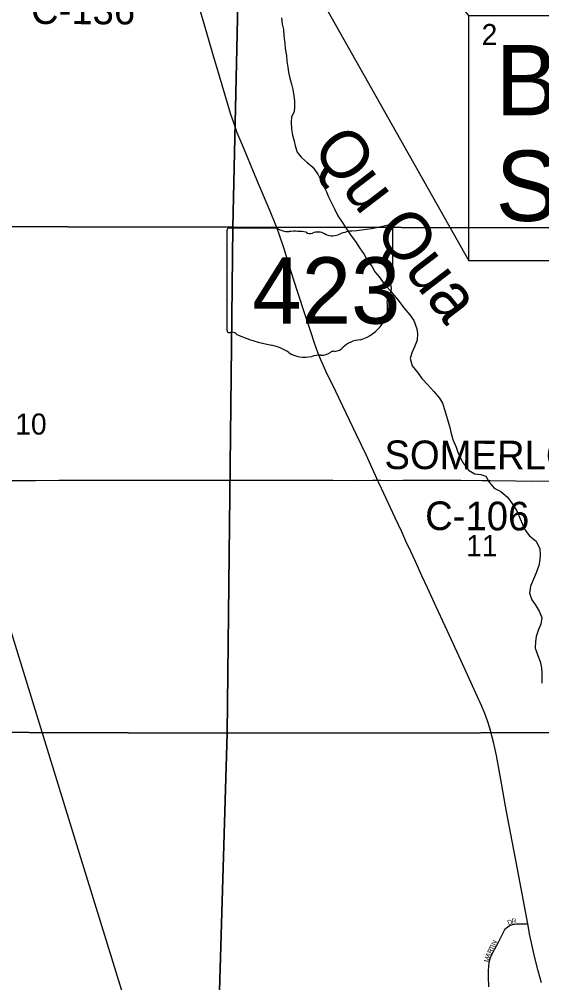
# Model space of a CAD drawing. Extents: x -97 to 34, y -21 to 22.
# Drawn here: x 6.147 to 7.185, y 14.954 to 16.869 of the extents above; entities that cross this region are included whole.
import ezdxf

# ---------------------------------------------------------------- set-up
doc = ezdxf.new("R2010")
doc.units = 0
for name, color, linetype in [('GM_X_County_Road', 7, 'Continuous'), ('GM_X_County_Road_Text', 7, 'Continuous'), ('GM_X_Minor_River', 7, 'Continuous'), ('GM_X_Minor_River_Text', 7, 'Continuous'), ('GM_X_Rail_Line', 7, 'Continuous'), ('GM_X_Section', 7, 'Continuous'), ('GM_X_Section_Text', 7, 'Continuous'), ('GM_X_State_Route', 7, 'Continuous'), ('GM_X_State_Shield', 7, 'Continuous'), ('GM_X_Township_Subdivision', 7, 'Continuous'), ('GM_X_Township_Subdivision_Text', 7, 'Continuous'), ('SH_Text', 7, 'Continuous')]:
    doc.layers.add(name, color=color, linetype=linetype)

msp = doc.modelspace()

# ---------------------------------------------------------------- linework, layer by layer
at = {"layer": 'GM_X_County_Road'}
for points in [[(6.0738, 15.9525), (6.1795, 15.9528), (6.2261, 15.9533), (6.2821, 15.9532), (6.366, 15.9535), (6.397, 15.9534), (6.4343, 15.9535), (6.5027, 15.9533), (6.5493, 15.9535), (6.5897, 15.9535), (6.6581, 15.9534), (6.7171, 15.9533), (6.77, 15.9531), (6.8197, 15.953), (6.8492, 15.9533), (6.8593, 15.9531)], [(6.8593, 15.9531), (6.8656, 15.9531), (6.8783, 15.953)], [(6.8783, 15.953), (6.8784, 15.953), (6.9095, 15.9531), (6.9344, 15.9533), (6.9655, 15.9533), (7.0245, 15.9532), (7.0672, 15.9528)], [(7.0672, 15.9528), (7.0836, 15.9526), (7.1333, 15.9518), (7.1644, 15.9517), (7.2017, 15.9518), (7.2328, 15.9521), (7.2825, 15.9526), (7.3074, 15.9525), (7.3187, 15.9525)]]:
    msp.add_lwpolyline(points, dxfattribs=at)
at = {"layer": 'GM_X_Minor_River'}
for points in [[(6.6681, 16.872), (6.6698, 16.8598), (6.672, 16.8492), (6.6729, 16.8366), (6.675, 16.8218), (6.6756, 16.8116), (6.6781, 16.7968), (6.679, 16.7865), (6.6808, 16.7744), (6.6821, 16.7641), (6.685, 16.7527), (6.6882, 16.7402), (6.6911, 16.7299), (6.6928, 16.717), (6.6939, 16.7075), (6.6944, 16.6954), (6.6932, 16.6855), (6.6885, 16.6754), (6.6872, 16.6651), (6.6881, 16.6507), (6.6903, 16.6393), (6.6935, 16.6275), (6.6953, 16.6176), (6.6992, 16.6051), (6.7071, 16.5955), (6.719, 16.5847), (6.7307, 16.5755), (6.7403, 16.5617), (6.7473, 16.5483), (6.7532, 16.5357), (6.7576, 16.5262), (6.7617, 16.5167), (6.7675, 16.5045), (6.7734, 16.4926), (6.7804, 16.4785)], [(6.7804, 16.4785), (6.7875, 16.4682), (6.796, 16.4552), (6.8068, 16.4391), (6.8153, 16.428), (6.8231, 16.415), (6.8328, 16.402), (6.8379, 16.3917), (6.8487, 16.3771), (6.8539, 16.3676), (6.8632, 16.3569), (6.8717, 16.3442), (6.8833, 16.3312), (6.8919, 16.3205), (6.9001, 16.3109), (6.9116, 16.2956), (6.9235, 16.2817), (6.9313, 16.2706), (6.9372, 16.2543), (6.9385, 16.2448), (6.938, 16.2315), (6.9329, 16.2183), (6.9274, 16.2067), (6.9238, 16.1953), (6.9278, 16.1805), (6.9401, 16.1663), (6.9475, 16.1556), (6.9591, 16.1429), (6.971, 16.1295), (6.9822, 16.1165), (6.9885, 16.1061), (6.9932, 16.0921), (6.9961, 16.0806), (6.9997, 16.0696), (7.003, 16.0582), (7.0058, 16.0464), (7.0091, 16.0342), (7.0153, 16.019), (7.0186, 16.0091), (7.0248, 15.9961), (7.03, 15.9866), (7.0401, 15.9732), (7.0525, 15.9658), (7.0646, 15.9645), (7.0744, 15.9613), (7.081, 15.9495), (7.0911, 15.9376), (7.1039, 15.9306), (7.1173, 15.9198), (7.1281, 15.9049), (7.1363, 15.8911), (7.1425, 15.8766), (7.1473, 15.8656), (7.1524, 15.8541), (7.1613, 15.843), (7.1744, 15.8322), (7.1814, 15.817), (7.1824, 15.8048), (7.1819, 15.795), (7.1798, 15.784), (7.1747, 15.7693), (7.1688, 15.7565), (7.1633, 15.7426), (7.1613, 15.7286), (7.1656, 15.7156), (7.1723, 15.7061), (7.1801, 15.6931), (7.1856, 15.6801), (7.1835, 15.6672), (7.1788, 15.6563), (7.1741, 15.6427), (7.1728, 15.6329), (7.1726, 15.6196), (7.1777, 15.6052), (7.1825, 15.593), (7.1849, 15.5801), (7.1855, 15.5691), (7.1854, 15.5596), (7.1857, 15.5501)]]:
    msp.add_lwpolyline(points, dxfattribs=at)
at = {"layer": 'GM_X_Rail_Line'}
msp.add_lwpolyline([(6.6358, 14.0177), (6.5035, 14.4453), (6.467, 14.5631), (6.2643, 15.2201), (6.0384, 15.9521), (5.7262, 16.962), (5.6052, 17.3534)], dxfattribs=at)
at = {"layer": 'GM_X_Section'}
for points in [[(5.5851, 17.4654), (6.5942, 17.463), (6.5713, 16.4562), (5.5865, 16.4584)], [(7.5928, 17.458), (7.5768, 16.4545), (6.5713, 16.4562), (6.5942, 17.463)], [(5.5865, 16.4584), (6.5713, 16.4562), (6.5605, 15.4504), (5.5758, 15.4541)], [(6.5713, 16.4562), (7.5768, 16.4545), (7.5679, 15.4518), (6.5605, 15.4504)], [(5.5758, 15.4541), (6.5605, 15.4504), (6.5304, 14.4478), (5.5564, 14.4458)], [(6.5605, 15.4504), (7.5679, 15.4518), (7.5552, 14.4456), (6.5304, 14.4478)]]:
    msp.add_lwpolyline(points, close=True, dxfattribs=at)
at = {"layer": 'GM_X_State_Route'}
msp.add_lwpolyline([(7.1851, 14.9544), (7.1782, 14.9783), (7.1718, 15.0043), (7.1652, 15.0339), (7.162, 15.0483), (7.1576, 15.0714), (7.1444, 15.1418), (7.1339, 15.1982), (7.1234, 15.2531), (7.1137, 15.3051), (7.1054, 15.3509), (7.0953, 15.4059), (7.0902, 15.4302), (7.0865, 15.4453), (7.0823, 15.4602), (7.0776, 15.475), (7.0723, 15.4896), (7.0653, 15.5068), (7.0621, 15.5139), (7.0606, 15.517), (7.058, 15.5228), (7.0249, 15.5956), (6.9938, 15.6629), (6.9759, 15.7014), (6.9586, 15.7394), (6.9475, 15.7635), (6.9345, 15.7916), (6.9254, 15.8113), (6.9157, 15.832), (6.9072, 15.8506), (6.8942, 15.8787), (6.8668, 15.9369), (6.8611, 15.9494), (6.8593, 15.9531), (6.8576, 15.9568), (6.837, 16.0021), (6.8176, 16.0434), (6.7761, 16.1297), (6.7565, 16.17), (6.7462, 16.1926), (6.7403, 16.2069), (6.7337, 16.2255), (6.7272, 16.2459), (6.7159, 16.2798), (6.7003, 16.3287), (6.6878, 16.3673), (6.6734, 16.4134), (6.663, 16.444), (6.6568, 16.4605), (6.6459, 16.4882), (6.6246, 16.5379), (6.6126, 16.5665), (6.6006, 16.5952), (6.5887, 16.6238), (6.5805, 16.6439), (6.5741, 16.6614), (6.5672, 16.682), (6.561, 16.7027), (6.5453, 16.7564), (6.5321, 16.801), (6.5146, 16.8606), (6.5035, 16.8979)], dxfattribs=at)
at = {"layer": 'GM_X_State_Shield'}
for p, q in [((6.56, 16.4505), (6.56, 16.2504)), ((6.6598, 16.454), (6.5633, 16.454)), ((6.8896, 16.3542), (6.8896, 16.4589)), ((6.8896, 16.3543), (6.8896, 16.3542))]:
    msp.add_line(p, q, dxfattribs=at)
for centre, major_axis, start_param, end_param in [((6.5638, 16.4509), (0.00382, 0), 1.712693, 3.28349), ((6.6828, 16.4772), (0.037, 0), 4.042523, 4.731795), ((6.7722, 16.7268), (0.3495, 0), 4.814394, 5.042369), ((6.886, 16.4593), (0.00367, 0), 6.141152, 7.989035), ((6.6951, 16.3416), (0.133, 0), 1.404758, 1.657858), ((6.7253, 16.452), (0.0107, 0), 3.836095, 5.185415), ((6.7409, 16.4288), (0.0222, 0), 0.950623, 2.079405), ((6.7696, 16.4606), (0.0267, 0), 4.081561, 5.145723), ((6.8168, 16.3928), (0.0703, 0), 1.699011, 2.107814), ((6.8857, 16.3538), (0.00393, 0), 5.05454, 6.418171), ((6.8888, 16.3465), (0.00568, 0), 1.883978, 3.671073), ((6.8527, 16.3333), (0.0341, 0), 5.934695, 6.695948), ((6.9028, 16.3104), (0.0248, 0), 2.387724, 3.262537), ((6.7918, 16.2971), (0.0874, 0), 5.101752, 6.440018), ((6.5639, 16.25), (0.00385, 0), 3.00124, 4.508301), ((6.5644, 16.2704), (0.0294, 0), 4.665946, 4.897461), ((6.5705, 16.2388), (0.0106, 0), 0.519207, 1.627899), ((6.7043, 16.4186), (0.2524, 0), 4.195997, 4.488961), ((6.629, 16.1605), (0.079, 0), 0.823519, 1.323587), ((6.8287, 16.1942), (0.0479, 0), 1.647645, 2.488434), ((6.7144, 16.2379), (0.0501, 0), 4.026481, 4.996735), ((6.7434, 16.1687), (0.0412, 0), 1.495662, 1.94098), ((6.7471, 16.2229), (0.0267, 0), 4.691044, 5.507374), ((6.7712, 16.2035), (0.00752, 0), 1.147584, 2.315152), ((6.768, 16.231), (0.0282, 0), 4.937069, 5.64225)]:
    msp.add_ellipse(centre, major_axis=major_axis, ratio=0.8, start_param=start_param, end_param=end_param, dxfattribs=at)
at = {"layer": 'GM_X_Township_Subdivision'}
msp.add_lwpolyline([(7.0802, 14.9466), (7.0801, 14.95), (7.0797, 14.9625), (7.0796, 14.9782), (7.0801, 14.9876), (7.081, 14.9938), (7.0826, 14.9999), (7.0846, 15.0058), (7.0885, 15.0143), (7.0986, 15.0338), (7.1086, 15.0534), (7.1116, 15.0589), (7.1134, 15.0614), (7.1155, 15.0636), (7.1179, 15.0656), (7.1205, 15.0673), (7.1232, 15.0688), (7.1258, 15.0699), (7.1287, 15.0706), (7.1318, 15.0711), (7.135, 15.0713), (7.1412, 15.0713), (7.1576, 15.0714)], dxfattribs=at)
at = {"layer": 'SH_Text'}
for points in [[(7.0407, 16.8772), (6.2148, 17.853), (7.0407, 16.3891)], [(7.0407, 16.8772), (9.1549, 16.8772), (9.1549, 16.3891), (7.0407, 16.3891)]]:
    msp.add_lwpolyline(points, close=True, dxfattribs=at)

# ---------------------------------------------------------------- texts
at = {"layer": 'GM_X_County_Road_Text'}
for s, rotation, p in [('C-136', 359.7223, (6.1704, 16.8602)), ('SOMERLOT', 359.8757, (6.8728, 15.9755)), ('C-106', 359.7271, (6.9537, 15.8544))]:
    msp.add_text(s, height=0.05682, rotation=rotation, dxfattribs=at).set_placement(p)
at = {"layer": 'GM_X_Minor_River_Text'}
msp.add_text('Qu Qua', height=0.09471, rotation=307.4337, dxfattribs=at).set_placement((6.7266, 16.6109))
at = {"layer": 'GM_X_Section_Text'}
for s, height, p in [('2', 0.0419, (7.066, 16.8181)), ('10', 0.04186, (6.1393, 16.044)), ('11', 0.04186, (7.0352, 15.8023))]:
    msp.add_text(s, height=height, rotation=0, dxfattribs=at).set_placement(p)
at = {"layer": 'GM_X_State_Shield'}
msp.add_text('423', height=0.13184, dxfattribs=at).set_placement((6.6104, 16.2645))
at = {"layer": 'GM_X_Township_Subdivision_Text'}
for s, rotation, p in [('D', 22.0449, (7.1194, 15.0689)), ('R', 9.2188, (7.1266, 15.0719)), ('N', 63.4347, (7.0934, 15.0277)), ('R', 63.6304, (7.0852, 15.0113)), ('T', 63.4349, (7.0886, 15.018)), ('I', 63.3958, (7.0915, 15.0239)), ('M', 73.5066, (7.0793, 14.9944)), ('A', 67.1229, (7.082, 15.0037))]:
    msp.add_text(s, height=0.00947, rotation=rotation, dxfattribs=at).set_placement(p)
at = {"layer": 'SH_Text'}
for s, p in [('BEGIN ACQUISITION', (7.0938, 16.6785)), ('S.L.M. 07.34', (7.0938, 16.4685))]:
    msp.add_text(s, height=0.14, dxfattribs=at).set_placement(p)

doc.saveas('drawing.dxf')
